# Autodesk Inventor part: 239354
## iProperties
Company: Mayer & Müller AG Schaltgeräte
Created: 2006-01
Part Number: 239354
Material: Cu
Description: Senkniet
Document SubType Name: Modeling
Designer: I.Baliuc
Manufacturer: Standard
Standards Organization: Custom
Density: 8.2 g/cm^3
HalbzeugNorm: DIN 661
Zweck: Spule
Abmessung: 3 x 10
Author: T.Messerschmitt
Keywords: 239354
Comments: DIN 661 - 3x10 - Cu
Revision Number: 239354
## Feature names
1. Drehung1 [Revolution]
